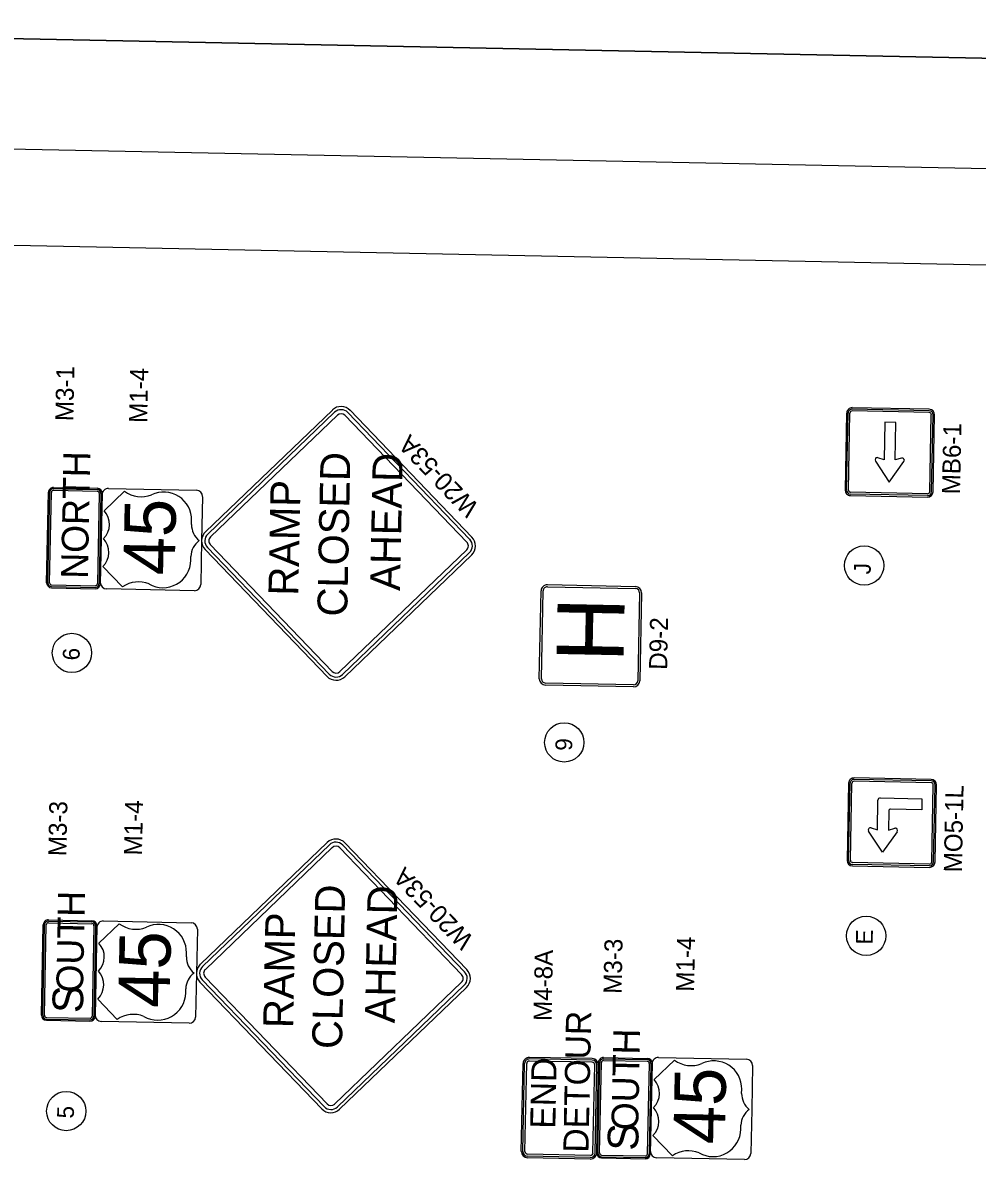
# Model space of a CAD drawing. Extents: x 311409 to 379449, y 121539 to 224848.
# Drawn here: x 327657 to 344745, y 204381 to 224848 of the extents above; entities that cross this region are included whole.
import ezdxf

# ---------------------------------------------------------------- set-up
doc = ezdxf.new("R2010")
doc.units = 0
for name, color, linetype in [('CA-TEXT', 7, 'Continuous'), ('P_RDWY_Text', 7, 'Continuous'), ('P_SGN_Cell', 7, 'Continuous'), ('PLT_Sheet_Border', 7, 'Continuous'), ('PLT_Sheet_Info', 7, 'Continuous')]:
    doc.layers.add(name, color=color, linetype=linetype)

msp = doc.modelspace()

# ---------------------------------------------------------------- linework, layer by layer
at = {"layer": 'CA-TEXT'}
for centre in [(342721, 215126), (328536, 213558), (337352, 211956), (342757, 208491), (328435, 205351)]:
    msp.add_circle(centre, 352, dxfattribs=at)
at = {"layer": 'P_RDWY_Text'}
msp.add_lwpolyline([(311409, 122868), (313463, 224848), (379449, 223519), (377396, 121539)], close=True, dxfattribs=at)
at = {"layer": 'P_SGN_Cell'}
for p, q in [((342408, 217857), (342380, 216479)), ((342407, 216478), (342434, 217856)), ((342440, 216478), (342467, 217856)), ((343885, 217866), (342507, 217894)), ((343886, 217899), (342508, 217927)), ((343886, 217925), (342509, 217953)), ((343896, 216448), (343924, 217826)), ((343929, 216448), (343957, 217826)), ((343955, 216447), (343983, 217825)), ((343094, 217692), (343081, 217020)), ((343291, 217688), (343094, 217692)), ((343277, 217016), (343291, 217688)), ((342923, 216997), (343171, 216620)), ((343081, 217020), (342968, 217056)), ((343171, 216620), (343434, 216987)), ((343391, 217048), (343277, 217016)), ((328083, 214816), (328116, 216437)), ((328106, 214816), (328138, 216436)), ((328136, 214816), (328168, 216436)), ((328207, 216502), (328987, 216487)), ((328207, 216472), (328986, 216457)), ((328208, 216525), (328988, 216509)), ((329023, 216418), (328991, 214799)), ((329053, 216418), (329021, 214798)), ((329076, 216417), (329043, 214798)), ((329044, 214820), (329075, 216395)), ((329476, 216456), (329111, 216107)), ((329190, 216505), (330765, 216473)), ((330875, 216358), (330859, 215571)), ((330875, 216358), (330875, 216358)), ((343855, 216377), (342477, 216405)), ((342477, 216378), (343855, 216351)), ((343856, 216410), (342478, 216438)), ((330678, 215861), (330680, 215932)), ((330859, 215571), (330843, 214784)), ((329091, 215107), (329441, 214742)), ((330665, 215218), (330667, 215289)), ((328171, 214725), (328951, 214709)), ((328172, 214748), (328952, 214732)), ((328173, 214778), (328952, 214762)), ((330728, 214674), (329154, 214705)), ((337051, 214782), (338626, 214750)), ((337051, 214744), (338625, 214712)), ((336905, 213097), (336937, 214671)), ((336942, 213096), (336974, 214671)), ((338699, 214636), (338667, 213061)), ((338736, 214635), (338705, 213061)), ((338590, 212950), (337015, 212982)), ((338591, 212988), (337016, 213020)), ((342443, 211223), (342416, 209845)), ((342442, 209844), (342470, 211222)), ((342475, 209844), (342502, 211221)), ((343921, 211265), (342543, 211293)), ((343921, 211232), (342543, 211260)), ((343922, 211291), (342544, 211319)), ((343931, 209814), (343959, 211192)), ((343964, 209814), (343992, 211191)), ((343990, 209813), (344018, 211191)), ((342958, 210389), (342969, 210923)), ((343009, 210962), (343757, 210947)), ((343757, 210947), (343753, 210750)), ((343162, 210729), (343155, 210385)), ((343753, 210750), (343196, 210761)), ((342846, 210425), (342958, 210389)), ((343155, 210385), (343269, 210417)), ((343049, 209990), (342801, 210366)), ((343312, 210356), (343049, 209990)), ((343891, 209776), (342513, 209803)), ((342512, 209744), (343890, 209717)), ((343891, 209743), (342513, 209771)), ((328115, 208776), (328895, 208761)), ((329098, 208757), (330672, 208725)), ((327991, 207067), (328023, 208688)), ((328013, 207068), (328046, 208688)), ((328043, 207067), (328076, 208687)), ((328114, 208724), (328894, 208708)), ((328115, 208754), (328895, 208738)), ((328931, 208670), (328898, 207050)), ((328961, 208669), (328928, 207050)), ((328983, 208669), (328951, 207049)), ((328951, 207072), (328983, 208646)), ((329383, 208708), (329019, 208358)), ((330782, 208610), (330767, 207823)), ((330782, 208610), (330782, 208610)), ((330586, 208112), (330587, 208184)), ((330767, 207823), (330751, 207035)), ((330573, 207469), (330574, 207541)), ((328999, 207358), (329349, 206994)), ((328079, 206999), (328859, 206983)), ((328079, 206977), (328859, 206961)), ((328080, 207029), (328860, 207013)), ((330636, 206925), (329061, 206957)), ((337854, 206290), (336729, 206313)), ((338057, 206310), (338836, 206294)), ((339039, 206313), (340614, 206281)), ((336582, 204628), (336614, 206203)), ((336610, 204627), (336642, 206202)), ((336648, 204627), (336680, 206201)), ((337852, 206225), (336727, 206247)), ((337853, 206262), (336728, 206285)), ((337866, 204602), (337898, 206177)), ((337904, 204601), (337936, 206176)), ((337932, 204601), (337965, 206222)), ((337932, 204601), (337964, 206175)), ((337955, 204602), (337987, 206221)), ((337985, 204601), (338017, 206221)), ((338055, 206257), (338835, 206242)), ((338056, 206287), (338836, 206272)), ((338872, 206203), (338839, 204584)), ((338902, 206203), (338869, 204583)), ((338925, 206202), (338892, 204583)), ((338893, 204628), (338925, 206202)), ((339325, 206264), (338961, 205914)), ((340724, 206166), (340708, 205379)), ((340724, 206166), (340724, 206166)), ((340528, 205668), (340529, 205740)), ((340708, 205379), (340692, 204591)), ((340515, 205025), (340516, 205097)), ((338940, 204914), (339290, 204550)), ((337818, 204519), (336693, 204541)), ((337817, 204491), (336693, 204513)), ((337819, 204556), (336694, 204579)), ((338020, 204510), (338800, 204495)), ((338021, 204563), (338801, 204547)), ((338021, 204533), (338801, 204517)), ((340578, 204481), (339003, 204513))]:
    msp.add_line(p, q, dxfattribs=at)
for points in [[(333200, 217911), (330928, 215729)], [(333239, 217870), (330968, 215688)], [(333289, 217818), (331017, 215636)], [(335606, 215546), (333424, 217817)], [(335657, 215595), (333476, 217866)], [(335698, 215635), (333517, 217906)], [(330922, 215411), (333104, 213139)], [(330963, 215450), (333145, 213179)], [(331014, 215500), (333197, 213228)], [(333333, 213225), (335605, 215407)], [(333382, 213174), (335654, 215356)], [(333422, 213133), (335694, 215315)], [(333107, 210163), (330836, 207980)], [(333147, 210121), (330875, 207939)], [(333196, 210070), (330925, 207888)], [(335513, 207797), (333332, 210068)], [(335565, 207847), (333383, 210118)], [(335606, 207886), (333425, 210157)], [(330922, 207751), (333104, 205480)], [(330829, 207662), (333011, 205391)], [(330870, 207702), (333053, 205430)], [(333240, 205477), (335512, 207659)], [(333290, 205425), (335562, 207607)], [(333329, 205384), (335601, 207566)]]:
    msp.add_lwpolyline(points, dxfattribs=at)
for centre, radius, start, end in [((333356, 217749), 225, 43.8462, 133.8462), ((333356, 217749), 168, 43.8462, 133.8462), ((333356, 217749), 96.4, 43.8462, 133.8462), ((342507, 217855), 98.4, 88.8462, 178.8462), ((342507, 217855), 72.2, 88.8462, 178.8462), ((342507, 217855), 39.4, 88.8462, 178.8462), ((343885, 217827), 39.4, 358.8462, 88.8462), ((343885, 217827), 98.4, 358.8462, 88.8462), ((343885, 217827), 72.2, 358.8462, 88.8462), ((342956, 217019), 39.4, 72.0436, 213.3759), ((343402, 217010), 39.4, 324.3166, 105.6488), ((328206, 216435), 90, 88.8462, 178.8462), ((328206, 216435), 67.5, 88.8462, 178.8462), ((328206, 216435), 37.5, 88.8462, 178.8462), ((328986, 216419), 37.5, 358.8462, 88.8462), ((328986, 216419), 67.5, 358.8462, 88.8462), ((328986, 216419), 90, 358.8462, 88.8462), ((329188, 216392), 112, 88.8462, 178.8462), ((329776, 216856), 500, 233.1143, 291.9873), ((330180, 215942), 500, 358.8462, 115.6928), ((330762, 216361), 112, 358.8462, 88.8462), ((342479, 216477), 98.4, 178.8462, 268.8462), ((342479, 216477), 72.2, 178.8462, 268.8462), ((342479, 216477), 98.4, 239.4497, 268.8462), ((342479, 216477), 39.4, 178.8462, 268.8462), ((343857, 216449), 72.2, 268.8462, 358.8462), ((343857, 216449), 98.4, 268.8462, 358.8462), ((343857, 216449), 39.4, 268.8462, 358.8462), ((328851, 215862), 357, 314.4191, 43.2734), ((331040, 215855), 362, 179.1885, 231.634), ((331084, 215567), 225, 133.8443, 223.8462), ((328841, 215362), 357, 314.4191, 43.2734), ((331028, 215280), 362, 126.0584, 178.5039), ((331084, 215567), 168, 133.8443, 223.8462), ((331084, 215567), 96.4, 133.8443, 223.8462), ((335538, 215477), 96.4, 313.8534, 44.4971), ((335538, 215477), 168, 313.8534, 44.4971), ((335538, 215477), 225, 313.8534, 44.4971), ((330165, 215228), 500, 240.0981, 358.8463), ((328173, 214815), 90, 179.6119, 268.8462), ((328173, 214815), 67.5, 178.8462, 268.8462), ((328173, 214815), 37.5, 178.8462, 268.8462), ((328953, 214799), 90, 268.8462, 358.8462), ((328953, 214799), 37.5, 268.8462, 358.8462), ((328953, 214799), 67.5, 268.8462, 358.8462), ((329156, 214818), 112, 178.8462, 268.8462), ((329727, 214332), 500, 67.7159, 124.7982), ((330731, 214786), 112, 268.8462, 358.8462), ((337049, 214669), 112, 88.8462, 178.8462), ((337049, 214669), 75, 88.8462, 178.8462), ((338624, 214637), 75, 358.8462, 88.8462), ((338624, 214637), 112, 358.8462, 88.8462), ((333266, 213295), 225, 223.8462, 313.8462), ((333266, 213295), 168, 223.8462, 313.8462), ((333266, 213295), 96.4, 223.8462, 313.8462), ((337017, 213095), 112, 178.8462, 268.8462), ((337017, 213095), 75, 178.8462, 268.8462), ((338592, 213063), 112, 268.8462, 358.8462), ((338592, 213063), 75, 268.8462, 358.8462), ((342542, 211221), 98.4, 88.8462, 178.8462), ((342542, 211221), 72.2, 88.8462, 178.8462), ((342542, 211221), 39.4, 88.8462, 178.8462), ((343920, 211193), 39.4, 358.8462, 88.8462), ((343920, 211193), 72.2, 358.8462, 88.8462), ((343920, 211193), 98.4, 358.8462, 88.8462), ((343008, 210922), 39.4, 88.8462, 178.8462), ((343195, 210728), 32.8, 88.8462, 178.8462), ((342834, 210388), 39.4, 72.0436, 213.3759), ((343280, 210379), 39.4, 324.3166, 105.6488), ((333263, 210000), 225, 43.8462, 133.8462), ((333263, 210000), 168, 43.8462, 133.8462), ((333263, 210000), 96.4, 43.8462, 133.8462), ((342514, 209843), 98.4, 178.8462, 268.8462), ((342514, 209843), 72.2, 178.8462, 268.8462), ((342514, 209843), 39.4, 178.8462, 268.8462), ((343892, 209815), 72.2, 268.8462, 358.8462), ((343892, 209815), 98.4, 268.8462, 358.8462), ((343892, 209815), 39.4, 268.8462, 358.8462), ((328113, 208686), 90, 88.8462, 178.8462), ((328893, 208671), 90, 358.8462, 88.8462), ((329095, 208644), 112, 88.8462, 178.8462), ((328113, 208686), 67.5, 88.8462, 178.8462), ((328113, 208686), 37.5, 88.8462, 178.8462), ((328893, 208671), 37.5, 358.8462, 88.8462), ((328893, 208671), 67.5, 358.8462, 88.8462), ((329683, 209108), 500, 233.1143, 291.9873), ((330087, 208194), 500, 358.8462, 115.6928), ((330670, 208612), 112, 358.8462, 88.8462), ((328759, 208113), 357, 314.4191, 43.2734), ((330947, 208107), 362, 179.1885, 231.634), ((330991, 207818), 225, 133.8443, 223.8462), ((330991, 207818), 168, 133.8443, 223.8462), ((328749, 207613), 357, 314.4191, 43.2734), ((330936, 207531), 362, 126.0584, 178.5039), ((330991, 207818), 96.4, 133.8443, 223.8462), ((335445, 207728), 96.4, 313.8534, 44.4971), ((335445, 207728), 168, 313.8534, 44.4971), ((335445, 207728), 225, 313.8534, 44.4971), ((330073, 207479), 500, 240.0981, 358.8463), ((328081, 207067), 90, 179.6119, 268.8462), ((328081, 207067), 67.5, 178.8462, 268.8462), ((328081, 207067), 37.5, 178.8462, 268.8462), ((328861, 207051), 67.5, 268.8462, 358.8462), ((328861, 207051), 90, 268.8462, 358.8462), ((328861, 207051), 37.5, 268.8462, 358.8462), ((329064, 207069), 112, 178.8462, 268.8462), ((329634, 206583), 500, 67.7159, 124.7982), ((330638, 207038), 112, 268.8462, 358.8462), ((336727, 206200), 112, 88.8468, 178.8468), ((338055, 206220), 90, 88.8462, 178.8462), ((339037, 206200), 112, 88.8462, 178.8462), ((336727, 206200), 84.4, 88.8468, 178.8468), ((336727, 206200), 46.9, 88.8468, 178.8468), ((337851, 206178), 46.9, 358.8468, 88.8468), ((337851, 206178), 84.4, 358.8468, 88.8468), ((337851, 206178), 112, 358.8468, 88.8468), ((338055, 206220), 67.5, 88.8462, 178.8462), ((338055, 206220), 37.5, 88.8462, 178.8462), ((338835, 206204), 37.5, 358.8462, 88.8462), ((338835, 206204), 90, 358.8462, 88.8462), ((338835, 206204), 67.5, 358.8462, 88.8462), ((339625, 206664), 500, 233.1143, 291.9873), ((340029, 205750), 500, 358.8462, 115.6928), ((340612, 206168), 112, 358.8462, 88.8462), ((338701, 205669), 357, 314.4191, 43.2734), ((340889, 205663), 362, 179.1885, 231.634), ((333174, 205546), 225, 223.8462, 313.8462), ((333174, 205546), 168, 223.8462, 313.8462), ((333174, 205546), 96.4, 223.8462, 313.8462), ((338690, 205169), 357, 314.4191, 43.2734), ((340877, 205087), 362, 126.0584, 178.5039), ((340015, 205035), 500, 240.0981, 358.8463), ((336695, 204626), 112, 178.8468, 268.8468), ((336695, 204626), 84.4, 178.8468, 268.8468), ((336695, 204626), 46.9, 178.8468, 268.8468), ((336695, 204626), 46.9, 178.8468, 187.6911), ((337820, 204603), 112, 268.8468, 358.8468), ((337820, 204603), 84.4, 268.8468, 358.8468), ((337820, 204603), 46.9, 268.8468, 358.8468), ((338022, 204600), 90, 179.6119, 268.8462), ((338022, 204600), 67.5, 178.8462, 268.8462), ((338022, 204600), 37.5, 178.8462, 268.8462), ((338802, 204584), 90, 268.8462, 358.8462), ((338802, 204584), 37.5, 268.8462, 358.8462), ((338802, 204584), 67.5, 268.8462, 358.8462), ((339005, 204625), 112, 178.8462, 268.8462), ((339576, 204139), 500, 67.7159, 124.7982), ((340580, 204594), 112, 268.8462, 358.8462)]:
    msp.add_arc(centre, radius, start, end, dxfattribs=at)
at = {"layer": 'PLT_Sheet_Border'}
for points in [[(377396, 121539), (379449, 223519), (313463, 224848), (311409, 122868)], [(375910, 122290), (377910, 221569), (314923, 222838), (312923, 123558)]]:
    msp.add_lwpolyline(points, close=True, dxfattribs=at)
at = {"layer": 'PLT_Sheet_Info'}
msp.add_line((376375, 219875), (316388, 221083), dxfattribs=at)

# ---------------------------------------------------------------- texts
at = {"layer": 'CA-TEXT'}
for s, p in [('J', (342838, 214966)), ('6', (328672, 213423)), ('9', (337492, 211804)), ('E', (342873, 208332)), ('5', (328570, 205216))]:
    msp.add_text(s, height=300, rotation=88.8468, dxfattribs=at).set_placement(p)
at = {"layer": 'P_SGN_Cell'}
for s, height, rotation, p in [('M3-1', 324, 88.8462, (328561, 217709)), ('M1-4', 324, 88.8462, (329883, 217677)), ('MB6-1', 324, 88.8462, (344438, 216398)), ('W20-53A', 324, 133.8468, (335841, 216186)), ('NORTH', 480, 88.8462, (328820, 214884)), ('CLOSED', 535.7, 88.8462, (333464, 214207)), ('AHEAD', 535.7, 88.8462, (334410, 214668)), ('RAMP', 535.7, 88.8462, (332589, 214581)), ('45', 920, 88.8462, (330375, 214944)), ('H', 1200, 88.8462, (338411, 213385)), ('D9-2', 324, 88.8462, (339193, 213254)), ('MO5-1L', 324, 88.8462, (344471, 209625)), ('M3-3', 324, 88.8462, (328436, 209915)), ('M1-4', 324, 88.8462, (329790, 209928)), ('W20-53A', 324, 133.8468, (335748, 208437)), ('CLOSED', 535.7, 88.8462, (333371, 206459)), ('OUTH', 480, 88.8462, (328734, 207471)), ('AHEAD', 535.7, 88.8462, (334317, 206920)), ('RAMP', 535.7, 88.8462, (332496, 206833)), ('45', 920, 88.8462, (330283, 207196)), ('M3-3', 324, 88.8462, (338377, 207449)), ('M1-4', 324, 88.8462, (339675, 207486)), ('M4-8A', 324, 88.8468, (337124, 206962)), ('S', 549, 88.8462, (328733, 207103)), ('DETOUR', 450, 88.8468, (337784, 204602)), ('OUTH', 480, 88.8462, (338675, 205004)), ('END', 450, 88.8468, (337191, 205031)), ('45', 920, 88.8462, (340224, 204752)), ('S', 549, 88.8462, (338675, 204637))]:
    msp.add_text(s, height=height, rotation=rotation, dxfattribs=at).set_placement(p)

doc.saveas('drawing.dxf')
